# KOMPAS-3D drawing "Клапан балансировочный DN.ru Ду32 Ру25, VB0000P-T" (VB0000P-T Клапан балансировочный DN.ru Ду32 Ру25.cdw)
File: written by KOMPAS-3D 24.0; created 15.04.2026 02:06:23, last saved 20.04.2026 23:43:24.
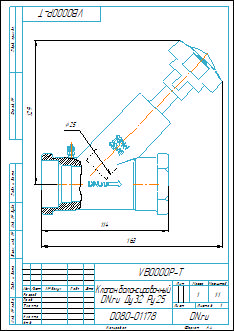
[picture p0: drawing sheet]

Document properties: Автор: DN.ru; Форматы листов документа: A4; Полное имя файла: VB0000P-T Клапан балансировочный DN.ru Ду32 Ру25.m3d; Масса: 1; Наименование: Клапан балансировочный DN.ru Ду32 Ру25; Количество листов документа: 1; Примечание: D080-01178

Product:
- Body: Тело 1  | qty 1
    Масса: 1.691588
- Part/product: Клапан балансировочный DN.ru Ду32 Ру25  | designation VB0000P-T
    Масса: 1
    Раздел спецификации: Прочие изделия
    Примечание: D080-01178

Views: Вид 1, Местный разрез 1, Вид:1
Referenced files in C:\Работа\VB0000P-T DN X PN 25 Клапан балансировочный DN.ru\DN15\: VB0000P-T DN15 PN25 Клапан балансировочный DN.ru.m3d
Referenced files in E:\Работа\Зайцев\АУТСОРС\Диман\Балансировка\VB0000P-T Клапан балансировочный DN.ru Ду15-50 Ру25\DN32\: VB0000P-T Клапан балансировочный DN.ru Ду32 Ру25.m3d
Referenced files in C:\Program Files\ASCON\KOMPAS-3D v24\Templates\: Чертеж_DN.ru.cdt
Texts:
  VB0000P-T
  Чертеж_DN.ru.cdt
  Клапан балансировочный
  DN.ru Ду32 Ру25
  Клапан балансировочный DN.ru Ду32 Ру25
  VB0000P-T Клапан балансировочный DN.ru Ду32 Ру25
Dimensions and other numbers on the sheet: 0; 3; 2; 4; 114; 129; 163; 1:1; 1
